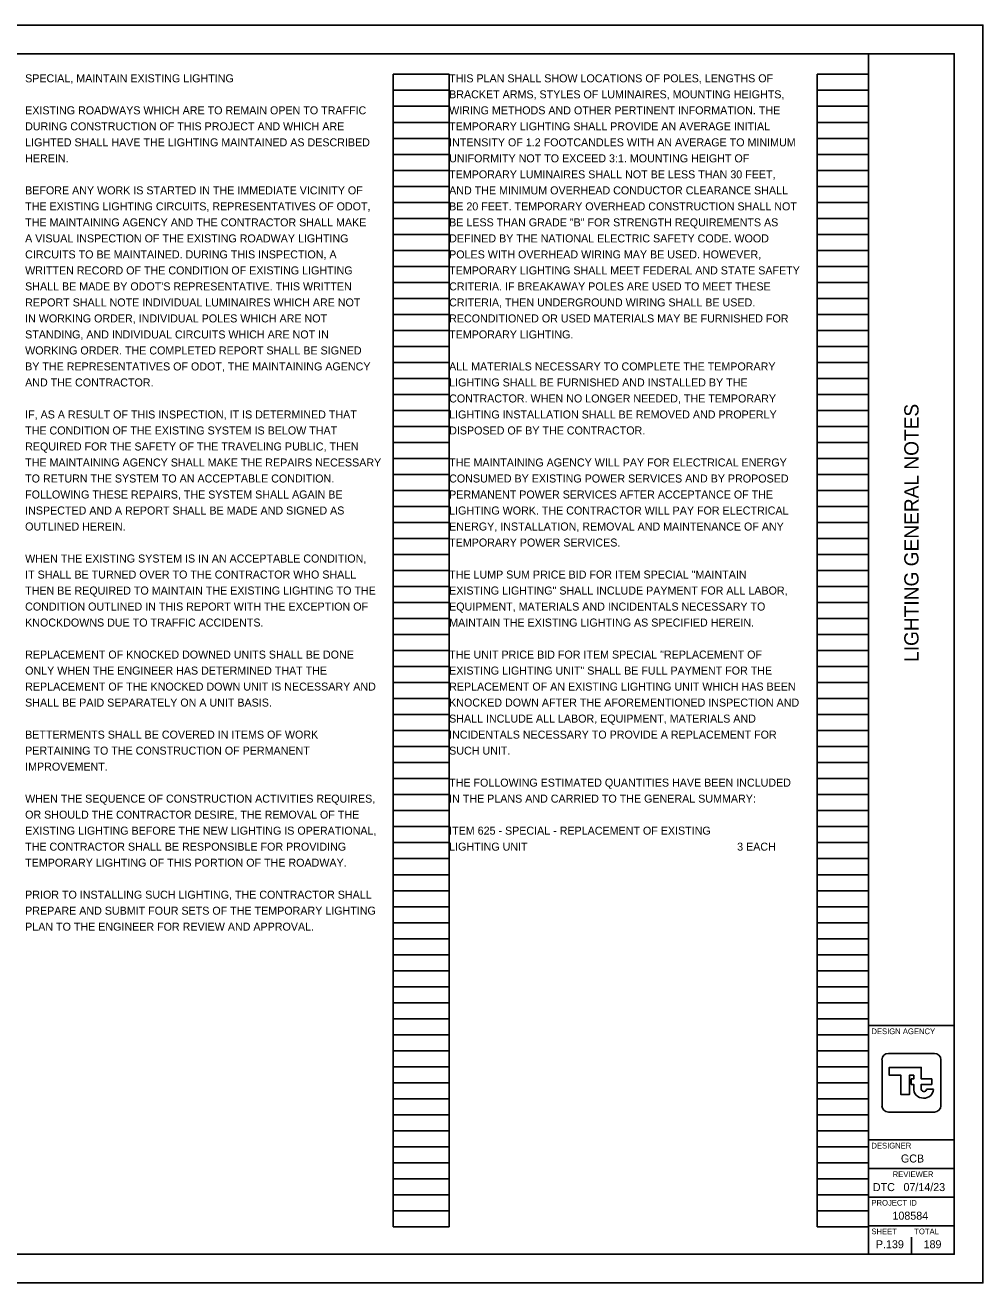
# Model space of a CAD drawing. Extents: x 0 to 59, y 0 to 22.
# Drawn here: x 17.24 to 34, y 0 to 22 of the extents above; entities that cross this region are included whole.
import ezdxf

# ---------------------------------------------------------------- set-up
doc = ezdxf.new("R2010")
doc.units = 0
for name, color, linetype in [('SH_Border', 7, 'Continuous'), ('SH_Cut_Line', 7, 'Continuous'), ('SH_Data', 7, 'Continuous'), ('SH_Text', 7, 'Continuous')]:
    doc.layers.add(name, color=color, linetype=linetype)

msp = doc.modelspace()

# ---------------------------------------------------------------- linework, layer by layer
at = {"layer": 'SH_Border'}
for p, q in [((32, 0.5), (32, 21.5)), ((32, 4.5), (33.5, 4.5)), ((32, 2.5), (33.5, 2.5)), ((32, 2), (33.5, 2)), ((32, 1.5), (33.5, 1.5)), ((32, 1), (33.5, 1))]:
    msp.add_line(p, q, dxfattribs=at)
msp.add_lwpolyline([(1.5, 21.5), (33.5, 21.5), (33.5, 0.5), (1.5, 0.5)], close=True, dxfattribs=at)
at = {"layer": 'SH_Cut_Line'}
msp.add_lwpolyline([(0, 0), (34, 0), (34, 22), (0, 22)], close=True, dxfattribs=at)
at = {"layer": 'SH_Data'}
for p, q in [((23.68, 0.98), (23.68, 21.14)), ((23.68, 21.14), (24.66, 21.14)), ((24.66, 0.98), (24.66, 21.14)), ((31.1, 0.98), (31.1, 21.14)), ((31.1, 21.14), (32, 21.14)), ((32, 0.98), (32, 21.14)), ((23.68, 20.86), (24.66, 20.86)), ((31.1, 20.86), (32, 20.86)), ((23.68, 20.58), (24.66, 20.58)), ((31.1, 20.58), (32, 20.58)), ((23.68, 20.3), (24.66, 20.3)), ((31.1, 20.3), (32, 20.3)), ((23.68, 20.02), (24.66, 20.02)), ((31.1, 20.02), (32, 20.02)), ((23.68, 19.74), (24.66, 19.74)), ((31.1, 19.74), (32, 19.74)), ((23.68, 19.46), (24.66, 19.46)), ((31.1, 19.46), (32, 19.46)), ((23.68, 19.18), (24.66, 19.18)), ((31.1, 19.18), (32, 19.18)), ((23.68, 18.9), (24.66, 18.9)), ((31.1, 18.9), (32, 18.9)), ((23.68, 18.62), (24.66, 18.62)), ((31.1, 18.62), (32, 18.62)), ((23.68, 18.34), (24.66, 18.34)), ((31.1, 18.34), (32, 18.34)), ((23.68, 18.06), (24.66, 18.06)), ((31.1, 18.06), (32, 18.06)), ((23.68, 17.78), (24.66, 17.78)), ((31.1, 17.78), (32, 17.78)), ((23.68, 17.5), (24.66, 17.5)), ((31.1, 17.5), (32, 17.5)), ((23.68, 17.22), (24.66, 17.22)), ((31.1, 17.22), (32, 17.22)), ((23.68, 16.94), (24.66, 16.94)), ((31.1, 16.94), (32, 16.94)), ((23.68, 16.66), (24.66, 16.66)), ((31.1, 16.66), (32, 16.66)), ((23.68, 16.38), (24.66, 16.38)), ((31.1, 16.38), (32, 16.38)), ((23.68, 16.1), (24.66, 16.1)), ((31.1, 16.1), (32, 16.1)), ((23.68, 15.82), (24.66, 15.82)), ((31.1, 15.82), (32, 15.82)), ((23.68, 15.54), (24.66, 15.54)), ((31.1, 15.54), (32, 15.54)), ((23.68, 15.26), (24.66, 15.26)), ((31.1, 15.26), (32, 15.26)), ((23.68, 14.98), (24.66, 14.98)), ((31.1, 14.98), (32, 14.98)), ((23.68, 14.7), (24.66, 14.7)), ((31.1, 14.7), (32, 14.7)), ((23.68, 14.42), (24.66, 14.42)), ((31.1, 14.42), (32, 14.42)), ((23.68, 14.14), (24.66, 14.14)), ((31.1, 14.14), (32, 14.14)), ((23.68, 13.86), (24.66, 13.86)), ((31.1, 13.86), (32, 13.86)), ((23.68, 13.58), (24.66, 13.58)), ((31.1, 13.58), (32, 13.58)), ((23.68, 13.3), (24.66, 13.3)), ((31.1, 13.3), (32, 13.3)), ((23.68, 13.02), (24.66, 13.02)), ((31.1, 13.02), (32, 13.02)), ((23.68, 12.74), (24.66, 12.74)), ((31.1, 12.74), (32, 12.74)), ((23.68, 12.46), (24.66, 12.46)), ((31.1, 12.46), (32, 12.46)), ((23.68, 12.18), (24.66, 12.18)), ((31.1, 12.18), (32, 12.18)), ((23.68, 11.9), (24.66, 11.9)), ((31.1, 11.9), (32, 11.9)), ((23.68, 11.62), (24.66, 11.62)), ((31.1, 11.62), (32, 11.62)), ((23.68, 11.34), (24.66, 11.34)), ((31.1, 11.34), (32, 11.34)), ((23.68, 11.06), (24.66, 11.06)), ((31.1, 11.06), (32, 11.06)), ((23.68, 10.78), (24.66, 10.78)), ((31.1, 10.78), (32, 10.78)), ((23.68, 10.5), (24.66, 10.5)), ((31.1, 10.5), (32, 10.5)), ((23.68, 10.22), (24.66, 10.22)), ((31.1, 10.22), (32, 10.22)), ((23.68, 9.94), (24.66, 9.94)), ((31.1, 9.94), (32, 9.94)), ((23.68, 9.66), (24.66, 9.66)), ((31.1, 9.66), (32, 9.66)), ((23.68, 9.38), (24.66, 9.38)), ((31.1, 9.38), (32, 9.38)), ((23.68, 9.1), (24.66, 9.1)), ((31.1, 9.1), (32, 9.1)), ((23.68, 8.82), (24.66, 8.82)), ((31.1, 8.82), (32, 8.82)), ((23.68, 8.54), (24.66, 8.54)), ((31.1, 8.54), (32, 8.54)), ((23.68, 8.26), (24.66, 8.26)), ((31.1, 8.26), (32, 8.26)), ((23.68, 7.98), (24.66, 7.98)), ((31.1, 7.98), (32, 7.98)), ((23.68, 7.7), (24.66, 7.7)), ((31.1, 7.7), (32, 7.7)), ((23.68, 7.42), (24.66, 7.42)), ((31.1, 7.42), (32, 7.42)), ((23.68, 7.14), (24.66, 7.14)), ((31.1, 7.14), (32, 7.14)), ((23.68, 6.86), (24.66, 6.86)), ((31.1, 6.86), (32, 6.86)), ((23.68, 6.58), (24.66, 6.58)), ((31.1, 6.58), (32, 6.58)), ((23.68, 6.3), (24.66, 6.3)), ((31.1, 6.3), (32, 6.3)), ((23.68, 6.02), (24.66, 6.02)), ((31.1, 6.02), (32, 6.02)), ((23.68, 5.74), (24.66, 5.74)), ((31.1, 5.74), (32, 5.74)), ((23.68, 5.46), (24.66, 5.46)), ((31.1, 5.46), (32, 5.46)), ((23.68, 5.18), (24.66, 5.18)), ((31.1, 5.18), (32, 5.18)), ((23.68, 4.9), (24.66, 4.9)), ((31.1, 4.9), (32, 4.9)), ((23.68, 4.62), (24.66, 4.62)), ((31.1, 4.62), (32, 4.62)), ((23.68, 4.34), (24.66, 4.34)), ((31.1, 4.34), (32, 4.34)), ((23.68, 4.06), (24.66, 4.06)), ((31.1, 4.06), (32, 4.06)), ((23.68, 3.78), (24.66, 3.78)), ((31.1, 3.78), (32, 3.78)), ((23.68, 3.5), (24.66, 3.5)), ((31.1, 3.5), (32, 3.5)), ((32.75, 3.5), (32.75, 3.5)), ((32.791, 3.415), (32.791, 3.415)), ((33.136, 3.385), (33.015, 3.385)), ((23.68, 3.22), (24.66, 3.22)), ((31.1, 3.22), (32, 3.22)), ((23.68, 2.94), (24.66, 2.94)), ((31.1, 2.94), (32, 2.94)), ((23.68, 2.66), (24.66, 2.66)), ((31.1, 2.66), (32, 2.66)), ((23.68, 2.38), (24.66, 2.38)), ((31.1, 2.38), (32, 2.38)), ((23.68, 2.1), (24.66, 2.1)), ((31.1, 2.1), (32, 2.1)), ((23.68, 1.82), (24.66, 1.82)), ((31.1, 1.82), (32, 1.82)), ((23.68, 1.54), (24.66, 1.54)), ((31.1, 1.54), (32, 1.54)), ((23.68, 1.26), (24.66, 1.26)), ((31.1, 1.26), (32, 1.26)), ((23.68, 0.98), (24.66, 0.98)), ((31.1, 0.98), (32, 0.98)), ((32.375, 0.675), (32.375, 0.675)), ((32.75, 0.5), (32.75, 0.8))]:
    msp.add_line(p, q, dxfattribs=at)
for points in [[(32.348, 4.014), (33.152, 4.014)], [(32.236, 3.099), (32.236, 3.901)], [(32.922, 3.399), (32.922, 3.47), (33.107, 3.47), (33.107, 3.568), (32.922, 3.568), (32.922, 3.768), (32.361, 3.768), (32.361, 3.632), (32.566, 3.632), (32.566, 3.294), (32.715, 3.294), (32.715, 3.63), (32.79, 3.63), (32.79, 3.568), (32.748, 3.568), (32.748, 3.47), (32.79, 3.47), (32.79, 3.415), (32.791, 3.415)], [(33.264, 3.901), (33.264, 3.099)], [(33.152, 2.986), (32.348, 2.986)]]:
    msp.add_lwpolyline(points, dxfattribs=at)
for centre, radius, start, end in [((32.348, 3.901), 0.113, 90, 180), ((33.152, 3.901), 0.113, 360, 90), ((32.949, 3.392), 0.16, 171.8856, 274.8323), ((32.968, 3.392), 0.0473, 171.8856, 350.9243), ((32.976, 3.392), 0.16, 265.1677, 357.3201), ((32.348, 3.099), 0.113, 180, 270), ((33.152, 3.099), 0.113, 270, 360)]:
    msp.add_arc(centre, radius, start, end, dxfattribs=at)

# ---------------------------------------------------------------- texts
msp.add_text('LIGHTING GENERAL NOTES', height=0.25, rotation=90, dxfattribs=at).set_placement((32.875, 10.862))
for s, height, p in [('DESIGN AGENCY', 0.1, (32.05, 4.35)), ('DESIGNER', 0.1, (32.05, 2.35)), ('GCB', 0.14, (32.566, 2.105)), ('REVIEWER', 0.1, (32.422, 1.85)), ('DTC', 0.14, (32.076, 1.605)), ('07/14/23', 0.14, (32.611, 1.605)), ('PROJECT ID', 0.1, (32.05, 1.35)), ('108584', 0.14, (32.418, 1.105)), ('SHEET', 0.1, (32.05, 0.85)), ('TOTAL', 0.1, (32.8, 0.85)), ('P.139', 0.14, (32.128, 0.605)), ('189', 0.14, (32.963, 0.605))]:
    msp.add_text(s, height=height, dxfattribs=at).set_placement(p)
at = {"layer": 'SH_Text'}
for s, p in [('SPECIAL, MAINTAIN EXISTING LIGHTING', (17.24, 21)), ('THIS PLAN SHALL SHOW LOCATIONS OF POLES, LENGTHS OF', (24.66, 21)), ('BRACKET ARMS, STYLES OF LUMINAIRES, MOUNTING HEIGHTS,', (24.66, 20.72)), ('EXISTING ROADWAYS WHICH ARE TO REMAIN OPEN TO TRAFFIC', (17.24, 20.44)), ('WIRING METHODS AND OTHER PERTINENT INFORMATION. THE', (24.66, 20.44)), ('DURING CONSTRUCTION OF THIS PROJECT AND WHICH ARE', (17.24, 20.16)), ('TEMPORARY LIGHTING SHALL PROVIDE AN AVERAGE INITIAL', (24.66, 20.16)), ('LIGHTED SHALL HAVE THE LIGHTING MAINTAINED AS DESCRIBED', (17.24, 19.88)), ('INTENSITY OF 1.2 FOOTCANDLES WITH AN AVERAGE TO MINIMUM', (24.66, 19.88)), ('HEREIN.', (17.24, 19.6)), ('UNIFORMITY NOT TO EXCEED 3:1. MOUNTING HEIGHT OF', (24.66, 19.6)), ('TEMPORARY LUMINAIRES SHALL NOT BE LESS THAN 30 FEET,', (24.66, 19.32)), ('BEFORE ANY WORK IS STARTED IN THE IMMEDIATE VICINITY OF', (17.24, 19.04)), ('AND THE MINIMUM OVERHEAD CONDUCTOR CLEARANCE SHALL', (24.66, 19.04)), ('THE EXISTING LIGHTING CIRCUITS, REPRESENTATIVES OF ODOT,', (17.24, 18.76)), ('BE 20 FEET. TEMPORARY OVERHEAD CONSTRUCTION SHALL NOT', (24.66, 18.76)), ('THE MAINTAINING AGENCY AND THE CONTRACTOR SHALL MAKE', (17.24, 18.48)), ('BE LESS THAN GRADE "B" FOR STRENGTH REQUIREMENTS AS', (24.66, 18.48)), ('A VISUAL INSPECTION OF THE EXISTING ROADWAY LIGHTING', (17.24, 18.2)), ('DEFINED BY THE NATIONAL ELECTRIC SAFETY CODE. WOOD', (24.66, 18.2)), ('CIRCUITS TO BE MAINTAINED. DURING THIS INSPECTION, A', (17.24, 17.92)), ('POLES WITH OVERHEAD WIRING MAY BE USED. HOWEVER,', (24.66, 17.92)), ('WRITTEN RECORD OF THE CONDITION OF EXISTING LIGHTING', (17.24, 17.64)), ('TEMPORARY LIGHTING SHALL MEET FEDERAL AND STATE SAFETY', (24.66, 17.64)), ("SHALL BE MADE BY ODOT'S REPRESENTATIVE. THIS WRITTEN", (17.24, 17.36)), ('CRITERIA. IF BREAKAWAY POLES ARE USED TO MEET THESE', (24.66, 17.36)), ('REPORT SHALL NOTE INDIVIDUAL LUMINAIRES WHICH ARE NOT', (17.24, 17.08)), ('CRITERIA, THEN UNDERGROUND WIRING SHALL BE USED.', (24.66, 17.08)), ('IN WORKING ORDER, INDIVIDUAL POLES WHICH ARE NOT', (17.24, 16.8)), ('RECONDITIONED OR USED MATERIALS MAY BE FURNISHED FOR', (24.66, 16.8)), ('STANDING, AND INDIVIDUAL CIRCUITS WHICH ARE NOT IN', (17.24, 16.52)), ('TEMPORARY LIGHTING.', (24.66, 16.52)), ('WORKING ORDER. THE COMPLETED REPORT SHALL BE SIGNED', (17.24, 16.24)), ('BY THE REPRESENTATIVES OF ODOT, THE MAINTAINING AGENCY', (17.24, 15.96)), ('ALL MATERIALS NECESSARY TO COMPLETE THE TEMPORARY', (24.66, 15.96)), ('AND THE CONTRACTOR.', (17.24, 15.68)), ('LIGHTING SHALL BE FURNISHED AND INSTALLED BY THE', (24.66, 15.68)), ('CONTRACTOR. WHEN NO LONGER NEEDED, THE TEMPORARY', (24.66, 15.4)), ('IF, AS A RESULT OF THIS INSPECTION, IT IS DETERMINED THAT', (17.24, 15.12)), ('LIGHTING INSTALLATION SHALL BE REMOVED AND PROPERLY', (24.66, 15.12)), ('THE CONDITION OF THE EXISTING SYSTEM IS BELOW THAT', (17.24, 14.84)), ('DISPOSED OF BY THE CONTRACTOR.', (24.66, 14.84)), ('REQUIRED FOR THE SAFETY OF THE TRAVELING PUBLIC, THEN', (17.24, 14.56)), ('THE MAINTAINING AGENCY SHALL MAKE THE REPAIRS NECESSARY', (17.24, 14.28)), ('THE MAINTAINING AGENCY WILL PAY FOR ELECTRICAL ENERGY', (24.66, 14.28)), ('TO RETURN THE SYSTEM TO AN ACCEPTABLE CONDITION.', (17.24, 14)), ('CONSUMED BY EXISTING POWER SERVICES AND BY PROPOSED', (24.66, 14)), ('FOLLOWING THESE REPAIRS, THE SYSTEM SHALL AGAIN BE', (17.24, 13.72)), ('PERMANENT POWER SERVICES AFTER ACCEPTANCE OF THE', (24.66, 13.72)), ('INSPECTED AND A REPORT SHALL BE MADE AND SIGNED AS', (17.24, 13.44)), ('LIGHTING WORK. THE CONTRACTOR WILL PAY FOR ELECTRICAL', (24.66, 13.44)), ('OUTLINED HEREIN.', (17.24, 13.16)), ('ENERGY, INSTALLATION, REMOVAL AND MAINTENANCE OF ANY', (24.66, 13.16)), ('TEMPORARY POWER SERVICES.', (24.66, 12.88)), ('WHEN THE EXISTING SYSTEM IS IN AN ACCEPTABLE CONDITION,', (17.24, 12.6)), ('IT SHALL BE TURNED OVER TO THE CONTRACTOR WHO SHALL', (17.24, 12.32)), ('THE LUMP SUM PRICE BID FOR ITEM SPECIAL "MAINTAIN', (24.66, 12.32)), ('THEN BE REQUIRED TO MAINTAIN THE EXISTING LIGHTING TO THE', (17.24, 12.04)), ('EXISTING LIGHTING" SHALL INCLUDE PAYMENT FOR ALL LABOR,', (24.66, 12.04)), ('CONDITION OUTLINED IN THIS REPORT WITH THE EXCEPTION OF', (17.24, 11.76)), ('EQUIPMENT, MATERIALS AND INCIDENTALS NECESSARY TO', (24.66, 11.76)), ('KNOCKDOWNS DUE TO TRAFFIC ACCIDENTS.', (17.24, 11.48)), ('MAINTAIN THE EXISTING LIGHTING AS SPECIFIED HEREIN.', (24.66, 11.48)), ('REPLACEMENT OF KNOCKED DOWNED UNITS SHALL BE DONE', (17.24, 10.92)), ('THE UNIT PRICE BID FOR ITEM SPECIAL "REPLACEMENT OF', (24.66, 10.92)), ('ONLY WHEN THE ENGINEER HAS DETERMINED THAT THE', (17.24, 10.64)), ('EXISTING LIGHTING UNIT" SHALL BE FULL PAYMENT FOR THE', (24.66, 10.64)), ('REPLACEMENT OF THE KNOCKED DOWN UNIT IS NECESSARY AND', (17.24, 10.36)), ('REPLACEMENT OF AN EXISTING LIGHTING UNIT WHICH HAS BEEN', (24.66, 10.36)), ('SHALL BE PAID SEPARATELY ON A UNIT BASIS.', (17.24, 10.08)), ('KNOCKED DOWN AFTER THE AFOREMENTIONED INSPECTION AND', (24.66, 10.08)), ('SHALL INCLUDE ALL LABOR, EQUIPMENT, MATERIALS AND', (24.66, 9.8)), ('BETTERMENTS SHALL BE COVERED IN ITEMS OF WORK', (17.24, 9.52)), ('INCIDENTALS NECESSARY TO PROVIDE A REPLACEMENT FOR', (24.66, 9.52)), ('PERTAINING TO THE CONSTRUCTION OF PERMANENT', (17.24, 9.24)), ('SUCH UNIT.', (24.66, 9.24)), ('IMPROVEMENT.', (17.24, 8.96)), ('THE FOLLOWING ESTIMATED QUANTITIES HAVE BEEN INCLUDED', (24.66, 8.68)), ('WHEN THE SEQUENCE OF CONSTRUCTION ACTIVITIES REQUIRES,', (17.24, 8.4)), ('IN THE PLANS AND CARRIED TO THE GENERAL SUMMARY:', (24.66, 8.4)), ('OR SHOULD THE CONTRACTOR DESIRE, THE REMOVAL OF THE', (17.24, 8.12)), ('EXISTING LIGHTING BEFORE THE NEW LIGHTING IS OPERATIONAL,', (17.24, 7.84)), ('ITEM 625 - SPECIAL - REPLACEMENT OF EXISTING', (24.66, 7.84)), ('THE CONTRACTOR SHALL BE RESPONSIBLE FOR PROVIDING', (17.24, 7.56)), ('LIGHTING UNIT', (24.66, 7.56)), ('3 EACH', (29.7, 7.56)), ('TEMPORARY LIGHTING OF THIS PORTION OF THE ROADWAY.', (17.24, 7.28)), ('PRIOR TO INSTALLING SUCH LIGHTING, THE CONTRACTOR SHALL', (17.24, 6.72)), ('PREPARE AND SUBMIT FOUR SETS OF THE TEMPORARY LIGHTING', (17.24, 6.44)), ('PLAN TO THE ENGINEER FOR REVIEW AND APPROVAL.', (17.24, 6.16))]:
    msp.add_text(s, height=0.14, dxfattribs=at).set_placement(p)

doc.saveas('drawing.dxf')
